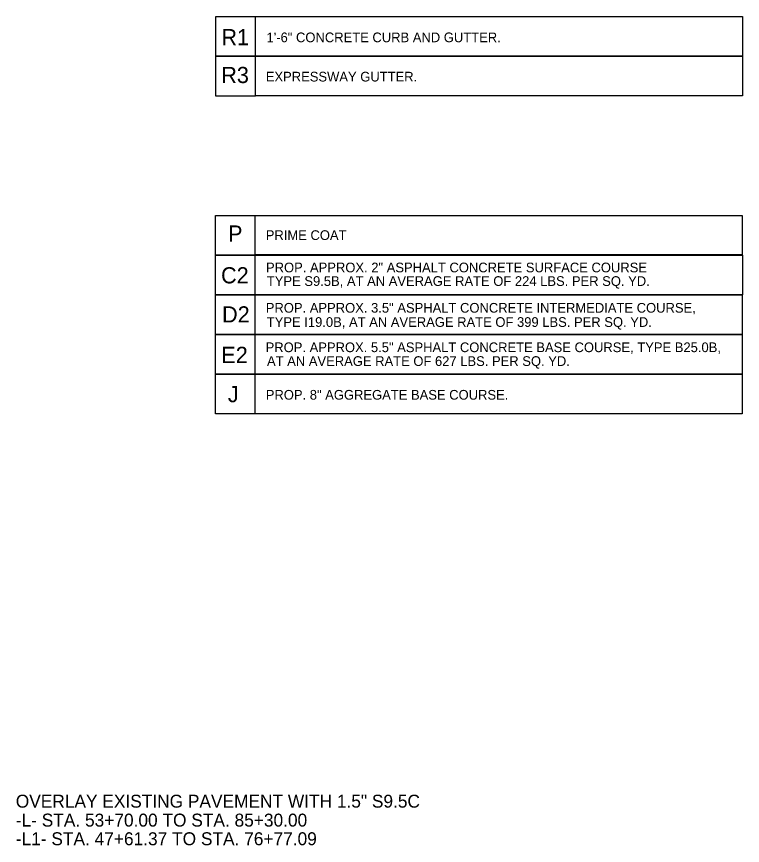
# Model space of a CAD drawing. Extents: x 573813 to 575363, y -54752 to -53123.
# Drawn here: x 574557.3 to 574659.4, y -53278.3 to -53161.8 of the extents above; entities that cross this region are included whole.
import ezdxf

# ---------------------------------------------------------------- set-up
doc = ezdxf.new("R2010")
doc.units = 0
doc.layers.add('Old_Level_1', color=7, linetype='Continuous')
doc.layers.add('Prop Pavement Schedule Description CELL', color=7, linetype='Continuous')

msp = doc.modelspace()

# ---------------------------------------------------------------- linework, layer by layer
at = {"layer": 'Prop Pavement Schedule Description CELL'}
for points in [[(574590.89, -53167.38), (574585.31, -53167.38), (574585.31, -53161.8), (574659.36, -53161.8), (574659.36, -53167.36), (574590.89, -53167.36), (574590.89, -53161.8)], [(574590.89, -53172.97), (574585.31, -53172.97), (574585.31, -53167.38), (574659.36, -53167.38), (574659.36, -53172.95), (574590.89, -53172.95), (574590.89, -53167.38)], [(574590.87, -53195.34), (574585.29, -53195.34), (574585.29, -53189.75), (574659.34, -53189.75), (574659.34, -53195.32), (574590.87, -53195.32), (574590.87, -53189.75)], [(574590.87, -53200.92), (574585.29, -53200.92), (574585.29, -53195.34), (574659.35, -53195.34), (574659.35, -53200.92), (574590.87, -53200.92), (574590.87, -53195.34)], [(574590.87, -53206.5), (574585.29, -53206.5), (574585.29, -53200.92), (574659.34, -53200.92), (574659.34, -53206.5), (574590.87, -53206.5), (574590.87, -53200.92)], [(574590.87, -53212.08), (574585.29, -53212.08), (574585.29, -53206.5), (574659.34, -53206.5), (574659.34, -53212.06), (574590.87, -53212.06), (574590.87, -53206.5)], [(574590.87, -53217.66), (574585.29, -53217.66), (574585.29, -53212.08), (574659.34, -53212.08), (574659.34, -53217.64), (574590.87, -53217.64), (574590.87, -53212.08)]]:
    msp.add_lwpolyline(points, dxfattribs=at)

# ---------------------------------------------------------------- texts
at = {"layer": 'Old_Level_1'}
msp.add_text('C2', height=2.274, dxfattribs=at).set_placement((574586.05, -53199.31))
for s, p in [('OVERLAY EXISTING PAVEMENT WITH 1.5" S9.5C', (574557.19, -53273.02)), ('-L- STA. 53+70.00 TO STA. 85+30.00', (574557.19, -53275.68)), ('-L1- STA. 47+61.37 TO STA. 76+77.09', (574557.19, -53278.3))]:
    msp.add_text(s, height=1.8192, rotation=360, dxfattribs=at).set_placement(p)
at = {"layer": 'Prop Pavement Schedule Description CELL'}
for s, height, p in [('R1', 2.274, (574586.1, -53165.83)), ('1\'-6" CONCRETE CURB AND GUTTER.', 1.3644, (574592.45, -53165.41)), ('R3', 2.274, (574586.08, -53171.15)), ('EXPRESSWAY GUTTER.', 1.3644, (574592.34, -53170.93)), ('P', 2.27, (574587.04, -53193.44)), ('PRIME COAT', 1.364, (574592.34, -53193.21)), ('PROP. APPROX. 2" ASPHALT CONCRETE SURFACE COURSE ', 1.3644, (574592.37, -53197.76)), ('TYPE S9.5B, AT AN AVERAGE RATE OF 224 LBS. PER SQ. YD. ', 1.3644, (574592.49, -53199.67)), ('PROP. APPROX. 3.5" ASPHALT CONCRETE INTERMEDIATE COURSE,', 1.3644, (574592.34, -53203.43)), ('D2', 2.274, (574586.19, -53204.81)), ('TYPE I19.0B, AT AN AVERAGE RATE OF 399 LBS. PER SQ. YD.', 1.3644, (574592.48, -53205.43)), ('PROP. APPROX. 5.5" ASPHALT CONCRETE BASE COURSE, TYPE B25.0B,', 1.3644, (574592.32, -53208.98)), ('E2', 2.274, (574586.09, -53210.5)), ('AT AN AVERAGE RATE OF 627 LBS. PER SQ. YD.', 1.3644, (574592.51, -53210.92)), ('J', 2.27, (574587.01, -53216.02)), ('PROP. 8" AGGREGATE BASE COURSE.', 1.3644, (574592.34, -53215.66))]:
    msp.add_text(s, height=height, dxfattribs=at).set_placement(p)

doc.saveas('drawing.dxf')
